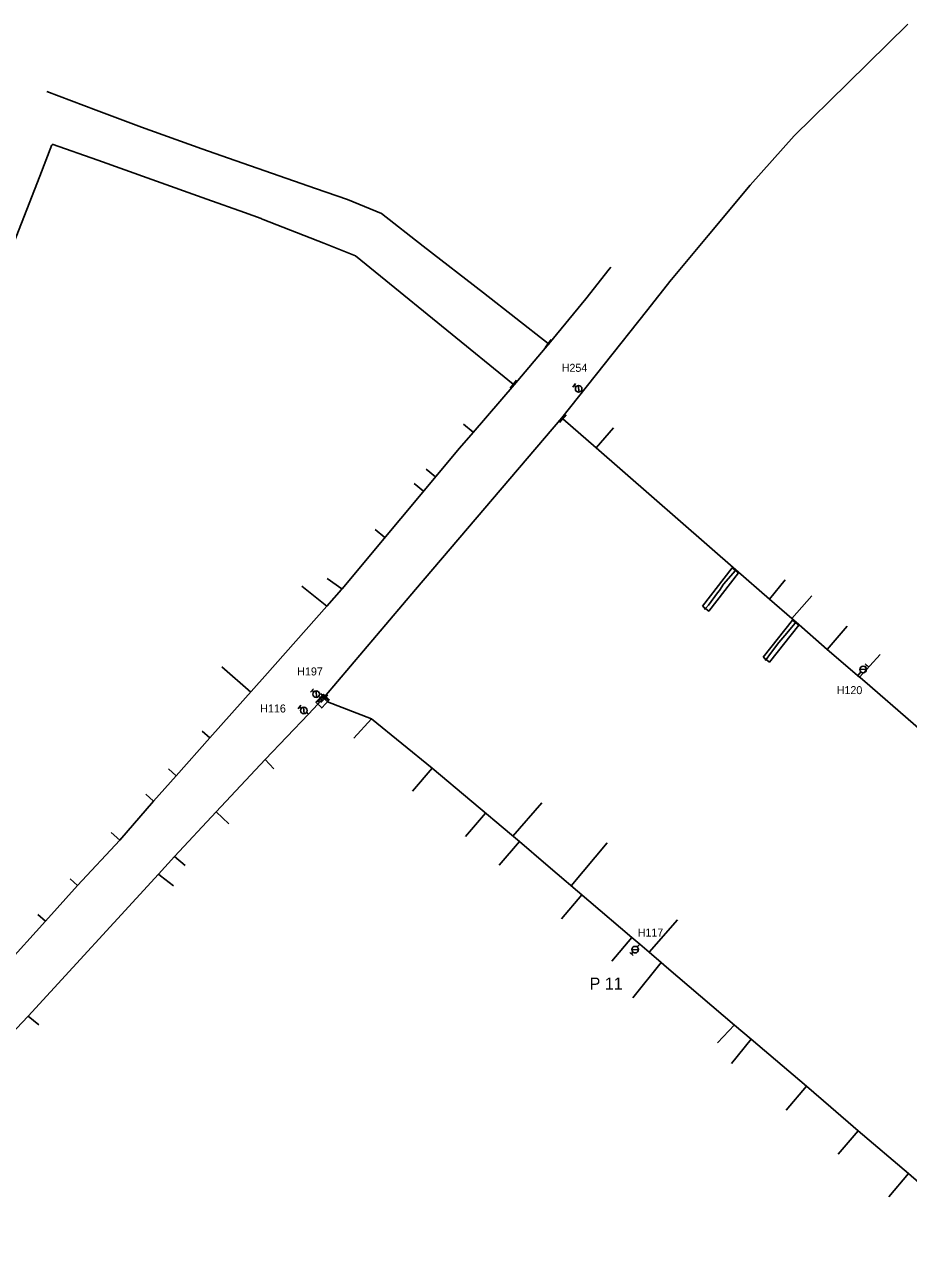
# Model space of a CAD drawing. Extents: x -548873 to -538270, y -1201997 to -1192514.
# Drawn here: x -544227.3 to -544006.3, y -1192903.4 to -1192599.8 of the extents above; entities that cross this region are included whole.
import ezdxf

# ---------------------------------------------------------------- set-up
doc = ezdxf.new("R2010")
doc.units = 0
for name, color, linetype in [('KN_HRAN_STÁTNÍ', 7, 'Continuous'), ('KN_PARC_Č', 7, 'Continuous'), ('KN_VKP_HRAN_SPORNÁ', 7, 'Continuous'), ('PK_PARC_Čv', 7, 'Continuous'), ('Vrstva 29', 7, 'Continuous'), ('Vrstva 37', 7, 'Continuous')]:
    doc.layers.add(name, color=color, linetype=linetype)

# ---------------------------------------------------------------- blocks, each defined once
blk = doc.blocks.new('160')
at = {"layer": 'KN_HRAN_STÁTNÍ'}
blk.add_circle((0, 0), 0.0458, dxfattribs=at)
blk = doc.blocks.new('147')
at = {"layer": 'KN_HRAN_STÁTNÍ'}
blk.add_line((0, 1.27), (0, -1.27), dxfattribs=at)
blk = doc.blocks.new('133')
at = {"layer": 'KN_HRAN_STÁTNÍ'}
for p, q in [((0.28, 0), (0, 0)), ((0.54, 0.58), (1.7, -0.58)), ((1.94, 0), (2.52, 0)), ((2.52, 0.58), (2.52, -0.58))]:
    blk.add_line(p, q, dxfattribs=at)
blk.add_circle((1.11, 0), 0.825, dxfattribs=at)
blk = doc.blocks.new('150')
at = {"layer": 'KN_HRAN_STÁTNÍ'}
blk.add_line((0, 1.27), (0, -1.27), dxfattribs=at)

msp = doc.modelspace()

# ---------------------------------------------------------------- linework, layer by layer
at = {"layer": 'KN_PARC_Č'}
for points in [[(-544115.108, -1192701.852), (-544117.547, -1192699.813)], [(-544084.409, -1192705.754), (-544080.086, -1192700.704)], [(-544124.528, -1192713), (-544126.875, -1192711.032)], [(-544127.531, -1192716.593), (-544129.884, -1192714.62)], [(-544137.203, -1192728.167), (-544139.6, -1192726.173)], [(-544049.48, -1192736.26), (-544049.6, -1192736.37), (-544052.59, -1192739.81), (-544053.58, -1192741.38), (-544054.08, -1192741.99), (-544056.29, -1192745.08), (-544057.06, -1192745.92), (-544057.44, -1192746.1)], [(-544147.916, -1192740.987), (-544151.601, -1192738.374)], [(-544041.089, -1192743.527), (-544037.142, -1192738.716)], [(-544151.701, -1192745.279), (-544157.989, -1192740.293)], [(-544035.465, -1192748.431), (-544030.486, -1192742.698)], [(-544034.41, -1192749.29), (-544034.54, -1192749.43), (-544034.68, -1192749.58), (-544037.24, -1192752.61), (-544038.75, -1192754.39), (-544040.79, -1192757.15), (-544041.88, -1192758.66), (-544042.26, -1192758.77)], [(-544026.658, -1192756.11), (-544021.656, -1192750.318)], [(-544018.547, -1192763.022), (-544013.438, -1192757.416)], [(-544170.738, -1192766.8), (-544177.906, -1192760.445)], [(-544140.517, -1192773.508), (-544144.964, -1192778.338)], [(-544180.921, -1192778.236), (-544182.839, -1192776.523)], [(-544167.157, -1192783.67), (-544164.947, -1192785.933)], [(-544189.348, -1192787.701), (-544191.29, -1192785.972)], [(-544125.419, -1192785.798), (-544130.281, -1192791.525)], [(-544194.995, -1192794.042), (-544196.938, -1192792.304)], [(-544105.202, -1192802.776), (-544097.969, -1192794.488)], [(-544179.362, -1192796.717), (-544176.226, -1192799.684)], [(-544112.013, -1192797.053), (-544117.032, -1192802.853)], [(-544203.431, -1192803.773), (-544205.566, -1192801.888)], [(-544103.571, -1192804.167), (-544108.654, -1192810.093)], [(-544090.618, -1192815.219), (-544081.616, -1192804.497)], [(-544189.812, -1192807.887), (-544187.124, -1192810.11)], [(-544193.761, -1192812.282), (-544193.258, -1192812.694), (-544189.995, -1192815.258)], [(-544214.004, -1192815.131), (-544215.886, -1192813.442)], [(-544088.002, -1192817.451), (-544093.035, -1192823.473)], [(-544222.052, -1192824.059), (-544223.907, -1192822.405)], [(-544071.16, -1192831.821), (-544064.03, -1192823.757)], [(-544075.452, -1192828.159), (-544080.513, -1192834.096)], [(-544068.144, -1192834.394), (-544075.225, -1192843.181)], [(-544226.384, -1192847.804), (-544223.69, -1192850.01)], [(-544049.835, -1192850.01), (-544054.099, -1192854.477)], [(-544045.646, -1192853.583), (-544050.599, -1192859.625)], [(-544031.857, -1192865.343), (-544036.893, -1192871.279)], [(-544018.921, -1192876.449), (-544023.891, -1192882.309)], [(-544006.357, -1192887.17), (-544011.273, -1192892.972)]]:
    msp.add_lwpolyline(points, dxfattribs=at)
at = {"layer": 'KN_VKP_HRAN_SPORNÁ'}
for points in [[(-544006.54, -1192599.845), (-544021.495, -1192614.523), (-544034.928, -1192627.706), (-544045.935, -1192640.095), (-544056.373, -1192652.652), (-544065.544, -1192663.685), (-544065.612, -1192663.77), (-544071.79, -1192671.549), (-544093.005, -1192698.259)], [(-544221.709, -1192616.67), (-544209.36, -1192621.296), (-544198.001, -1192625.551), (-544182.905, -1192630.953), (-544176.256, -1192633.332), (-544154.529, -1192640.858), (-544146.538, -1192643.623), (-544138.03, -1192647.173), (-544127.61, -1192655.293), (-544112.578, -1192667.008), (-544096.368, -1192679.64)], [(-544280.818, -1192747.918), (-544279.941, -1192746.759), (-544273.584, -1192738.196), (-544267.929, -1192731.322), (-544267.927, -1192731.32), (-544262.457, -1192724.482), (-544256.786, -1192717.392), (-544254.009, -1192713.92), (-544251.247, -1192710.466), (-544250.63, -1192709.045), (-544247.826, -1192701.476), (-544242.254, -1192686.827), (-544240.108, -1192681.097), (-544238.935, -1192677.963), (-544235.878, -1192669.8), (-544233.195, -1192662.885), (-544232.579, -1192661.296), (-544232.578, -1192661.294), (-544223.474, -1192637.829), (-544220.423, -1192629.965)], [(-544220.38, -1192629.855), (-544208.94, -1192633.797), (-544195.409, -1192638.638), (-544181.709, -1192643.539), (-544172.296, -1192646.92), (-544168.136, -1192648.395), (-544168.005, -1192648.447), (-544167.588, -1192648.612), (-544152.444, -1192654.6), (-544144.545, -1192657.723), (-544138.257, -1192662.838), (-544105.113, -1192689.796)], [(-544096.211, -1192679.763), (-544086.947, -1192668.504), (-544081.122, -1192661.027), (-544080.756, -1192660.532)], [(-544096.211, -1192679.763), (-544104.88, -1192689.985)], [(-544096.368, -1192679.64), (-544096.211, -1192679.763)], [(-544104.88, -1192689.985), (-544115.108, -1192701.853), (-544118.543, -1192705.838), (-544147.913, -1192740.983), (-544148.022, -1192741.114), (-544151.701, -1192745.279), (-544167.192, -1192762.817), (-544180.921, -1192778.236), (-544189.348, -1192787.701), (-544194.995, -1192794.042), (-544203.431, -1192803.773), (-544214.004, -1192815.131), (-544222.052, -1192824.059), (-544232.086, -1192835.19), (-544262.159, -1192868.552)], [(-544105.113, -1192689.796), (-544104.88, -1192689.985)], [(-544093.005, -1192698.259), (-544129.523, -1192741.182), (-544152.292, -1192767.946)], [(-544092.765, -1192698.469), (-544093.005, -1192698.259)], [(-543948.707, -1192823.901), (-543957.673, -1192816.118), (-543970.646, -1192804.727), (-543972.53, -1192803.073), (-544005.186, -1192774.648), (-544017.286, -1192764.116), (-544018.343, -1192763.196), (-544018.547, -1192763.022), (-544026.658, -1192756.11), (-544034.41, -1192749.29), (-544035.465, -1192748.431), (-544041.089, -1192743.527), (-544049.48, -1192736.26), (-544084.409, -1192705.754), (-544092.765, -1192698.469)], [(-544152.577, -1192768.254), (-544153.983, -1192769.772), (-544156.29, -1192772.311), (-544167.157, -1192783.67), (-544179.363, -1192796.717), (-544189.816, -1192807.891), (-544193.763, -1192812.284), (-544226.383, -1192847.804), (-544229.225, -1192850.898), (-544239.465, -1192861.842), (-544250.308, -1192873.432), (-544266.968, -1192892.289), (-544277.138, -1192905.06), (-544282.132, -1192911.33), (-544290.552, -1192921.011), (-544298.024, -1192929.601), (-544304.543, -1192936.293), (-544322.936, -1192955.028), (-544323.415, -1192955.516)], [(-544152.292, -1192767.946), (-544152.577, -1192768.254)], [(-544152.577, -1192768.254), (-544152.325, -1192768.497)], [(-544152.325, -1192768.497), (-544151.575, -1192769.223), (-544140.519, -1192773.507), (-544125.419, -1192785.798), (-544105.532, -1192802.494), (-544103.571, -1192804.167), (-544096.951, -1192809.816), (-544075.452, -1192828.159), (-544073.508, -1192829.818), (-544071.137, -1192831.841), (-544068.144, -1192834.394), (-544066.8, -1192835.541), (-544049.831, -1192850.013), (-544045.643, -1192853.585), (-544031.857, -1192865.343), (-544025.774, -1192870.531), (-544018.921, -1192876.449), (-544006.358, -1192887.169), (-543987.78, -1192903.34)]]:
    msp.add_lwpolyline(points, dxfattribs=at)
at = {"layer": 'PK_PARC_Čv'}
for points in [[(-544087.817, -1192691.728), (-544087.894, -1192691.667)], [(-544019.035, -1192762.606), (-544018.435, -1192761.957)], [(-544152.57, -1192767.29), (-544151.1, -1192768.71), (-544152.98, -1192770.74), (-544154.45, -1192769.32), (-544152.57, -1192767.29)], [(-544152.917, -1192768.621), (-544153.529, -1192768.054)], [(-544156.29, -1192772.311), (-544156.57, -1192772.08)], [(-544073.508, -1192829.818), (-544073.944, -1192830.329)]]:
    msp.add_lwpolyline(points, dxfattribs=at)
at = {"layer": 'Vrstva 37'}
for points in [[(-544057.848, -1192745.304), (-544050.388, -1192735.754), (-544048.812, -1192736.986), (-544056.272, -1192746.536), (-544057.848, -1192745.304)], [(-544042.663, -1192758.038), (-544035.323, -1192748.808), (-544033.757, -1192750.052), (-544041.097, -1192759.282), (-544042.663, -1192758.038)]]:
    msp.add_lwpolyline(points, dxfattribs=at)

# ---------------------------------------------------------------- block references
at = {"layer": 'PK_PARC_Čv'}
for name, p, xscale, yscale, rotation in [('133', (-544087.894, -1192691.667), 1.000000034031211, 1.0000000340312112, 141.99999959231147), ('133', (-544018.435, -1192761.957), 1.0000000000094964, 1.0000000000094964, 47.99999869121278), ('133', (-544153.529, -1192768.054), 1.0000000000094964, 1.0000000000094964, 137.9999986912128), ('133', (-544156.57, -1192772.08), 1.000000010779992, 1.0000000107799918, 141.00000108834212), ('150', (-544153.21, -1192768.349), 1.0000000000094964, 1.0000000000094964, -42.000001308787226), ('133', (-544073.944, -1192830.329), 1.0000000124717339, 1.0000000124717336, -130.0000013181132)]:
    msp.add_blockref(name, p, dxfattribs=dict(at, xscale=xscale, yscale=yscale, rotation=rotation))
at = {"layer": 'Vrstva 29'}
for name, p, xscale, yscale, rotation in [('147', (-544096.368, -1192679.64), 0.9999999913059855, 0.9999999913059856, 142.99999806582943), ('160', (-544096.211, -1192679.763), 1.000000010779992, 1.0000000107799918, -128.99999891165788), ('147', (-544105.113, -1192689.796), 1.000000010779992, 1.0000000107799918, 141.00000108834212), ('160', (-544104.88, -1192689.985), 1.0000000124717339, 1.0000000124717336, -130.0000013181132), ('147', (-544092.765, -1192698.469), 1.0000000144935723, 1.0000000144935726, 139.00000089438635), ('160', (-544093.005, -1192698.259), 1.0000000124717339, 1.0000000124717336, -130.0000013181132), ('147', (-544152.292, -1192767.946), 1.0000000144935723, 1.0000000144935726, -130.99999910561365), ('147', (-544152.325, -1192768.497), 1.0000000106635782, 1.0000000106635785, 135.99999834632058), ('160', (-544152.577, -1192768.254), 1.00000001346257, 1.0000000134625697, 91.99999990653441)]:
    msp.add_blockref(name, p, dxfattribs=dict(at, xscale=xscale, yscale=yscale, rotation=rotation))

# ---------------------------------------------------------------- texts
at = {"layer": 'PK_PARC_Čv'}
for s, height, p in [('H254', 2, (-544093.004, -1192686.727)), ('H197', 2, (-544159.099, -1192762.624)), ('H120', 2, (-544024.275, -1192767.297)), ('H116', 2, (-544168.35, -1192771.89)), ('H117', 2, (-544074.014, -1192827.889)), ('P 11', 3, (-544086.024, -1192841.149))]:
    msp.add_text(s, height=height, dxfattribs=at).set_placement(p)

doc.saveas('drawing.dxf')
